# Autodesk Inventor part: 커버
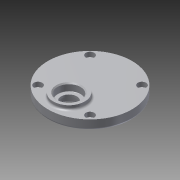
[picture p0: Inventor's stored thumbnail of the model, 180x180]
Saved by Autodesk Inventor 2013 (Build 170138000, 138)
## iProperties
Created: 2015-07
Part Number: 커버
Material: 알루미늄 6061
Document SubType Name: Modeling
Designer: user
Density: 1 g/cm^3
Author: user
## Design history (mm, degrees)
sketch "스케치1"
  geometry: C1 r 40 at (0, 0); 1 further point
  constraints: 1 centre point, 1 coincident
  dimensions: "d0" = 40 radius of C1
extrude "돌출1" new body sketch "스케치1" distance "d1" = 9; taper "d2" = 0 deg
sketch "스케치2"
  geometry: L1 (0, 0)-(0, -20); C1 r 40 at (0, 0) reference; C2 r 15 at (0, -20)
  constraints: 2 end point, 1 centre point, 1 coincident, 1 vertical
  dimensions: "d3" = 20 distance of L1.start L1.end; "d4" = 15 radius of C2
extrude "돌출2" join sketch "스케치2" distance "d5" = 4; taper "d6" = 0 deg
sketch "스케치3"
  geometry: L1 (0, 0)-(0, 11); L2 (0, 0)-(0, -20); C1 r 40 at (0, 0) reference; C2 r 14 at (0, 11); C3 r 14 at (0, -20)
  constraints: 4 end point, 2 centre point, 2 coincident, 1 collinear, 1 vertical
  dimensions: "d7" = 11 distance of L1.start L1.end; "d8" = 20 distance of L1.start L2.end; "d9" = 14 radius of C2; "d10" = 14 radius of C3
extrude "돌출3" join sketch "스케치3" distance "d11" = 3; taper "d12" = 0 deg
sketch "스케치4"
  geometry: C1 r 15 at (0, 0) reference; 1 further point
hole "구멍1" sketch "스케치4" at (0, 0) diameter "d13" = 15; stored, may be unused: countersink angle "d17" = 90 deg, drill point angle "d19" = 0 deg; dims "d14" = 6, "d15" = 22, "d16" = 7, "d18" = 9
sketch "스케치5"
  geometry: C1 r 14 at (0, 0) reference; 1 further point
hole "구멍2" sketch "스케치5" at (0, 0) diameter "d20" = 22; stored, may be unused: countersink angle "d24" = 90 deg, drill point angle "d26" = 0 deg; dims "d21" = 6, "d22" = 22, "d23" = 7, "d25" = 7
sketch "스케치6"
  geometry: C1 r 14 at (0, 0) reference; 1 further point
hole "구멍3" sketch "스케치6" at (0, 0) diameter "d27" = 18; stored, may be unused: countersink angle "d31" = 90 deg, drill point angle "d33" = 0 deg; dims "d28" = 6, "d29" = 22, "d30" = 7, "d32" = 8
chamfer "모따기1" distance "d34" = 1; stored, may be unused: second distance "d35" = 2, angle "d36" = 45 deg
fillet "모깎기1" dims "d37" = 0.3
fillet "모깎기2" dims "d38" = 2
fillet "모깎기3" dims "d39" = 0.3
sketch "스케치7"
  geometry: C1 r 40 at (0, 0) reference; 4 further points
  constraints: 5 other
  dimensions: "d43" = 360 deg dimension on C1.centre point (-24.749, 24.749) (derived)
hole "구멍4" sketch "스케치7" at (-24.749, 24.749), (-24.749, -24.749), (24.749, -24.749), (24.749, 24.749) diameter "d45" = 4.5; stored, may be unused: countersink angle "d49" = 90 deg, drill point angle "d51" = 0 deg; dims "d46" = 6, "d47" = 8, "d48" = 4.4, "d50" = 8
fillet "모깎기4" dims "d52" = 2
fillet "모깎기5" dims "d53" = 2
node "솔리드1"
